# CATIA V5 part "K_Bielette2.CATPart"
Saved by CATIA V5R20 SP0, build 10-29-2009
Part number: Bielette2
Bounding box of the stored display mesh (mm): x -21 to 21, y 241.852 to 249.04, z 74.873 to 106.343
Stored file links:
  G:\Khaled_CFAO_2011\ST2M\ST2M_GR1\hgrenier\Khaled\CAD_ThinkMOTION\K_Bielette2.CATPart
  C:\Users\Tom\Documents\Cours 2A\CFAO\Projet thinkmotion\Hugo\porte_outil.CATProduct
  G:\Khaled_CFAO_2011\ST2M\ST2M_GR1\hgrenier\Khaled\CAD_ThinkMOTION\K_Squelette.CATPart
  G:\Khaled_CFAO_2011\ST2M\ST2M_GR1\hgrenier\Khaled\CAD_ThinkMOTION\K_Godet.CATPart
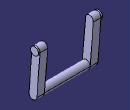
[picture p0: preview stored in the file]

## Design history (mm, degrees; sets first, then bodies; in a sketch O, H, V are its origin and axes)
External parameters (linked from other documents)
  External.Rayon = 2.5697 mm
Set1
  Plane1 "Plan_godet": linked copy from another document
  Point1 "Centre_godet/bielette2": linked copy from another document
  DatumSurface1: linked copy from another document
  Point2 "Centre_bielette2/tête": linked copy from another document
  Plane2 "plan_sym": linked copy from another document
Body1 (main body)
  Sketch1 on Plane1, origin (21, 0, 0), H (0, 1, 0), V (0, 0, 1)
    circle A1 centre (246.47, 103.773) radius 2.5697
    point P1 (246.47, 103.773)
    reference projected point E1 (246.47, 103.773) from Point1
    radius A1 = 2.5697 {= External.Rayon}
    coincidence: P1 E1
  Pad1: profile Sketch1, direction (-1, 0, 0), length 1
  Sketch2 on end face of Pad1, origin (20, 0, 0), H (0, -1, 0), V (0, 0, 1)
    construction line L1 (-246.47, 103.773) -> (-244.422, 77.441)
    point P1 (-246.47, 103.773)
    point P2 (-244.422, 77.441)
    line L2 (-243.908, 103.9723) -> (-241.86, 77.6403)
    line L3 (-246.984, 77.2417) -> (-249.032, 103.5737)
    arc A1 centre (-244.422, 77.441) radius 2.5697 from (-241.86, 77.6403) to (-246.984, 77.2417) cw
    arc A2 centre (-246.47, 103.773) radius 2.5697 from (-249.032, 103.5737) to (-243.908, 103.9723) cw
    reference projected point E1 (-246.47, 103.773) from Point1
    reference projected point E2 (-244.422, 77.441) from Point2
    distance L1 L2 = 2.5697 {= Sketch1.radius(A1)}
    tangency: A1 L2, A2 L2, A1 L3, A2 L3
    coincidence: P1 E1, P2 E2
  Pad2: profile Sketch2, direction (-1, 0, 0), length 5
  Sketch3 on end face of Pad2, origin (15, 0, 0), H (0, -1, 0), V (0, 0, 1)
    circle A1 centre (-244.422, 77.441) radius 2.5697
    point P1 (-244.422, 77.441)
    reference projected point E1 (-244.422, 77.441) from Point2
    radius A1 = 2.5697 {= Sketch1.radius(A1)}
    coincidence: P1 E1
  Pad3: profile Sketch3, direction (-1, 0, 0), up to Plane2
  Mirror1: of the body so far, about Plane2
Relations
  Sketch3.radius(A1) = Sketch1.radius(A1) (deactivated)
